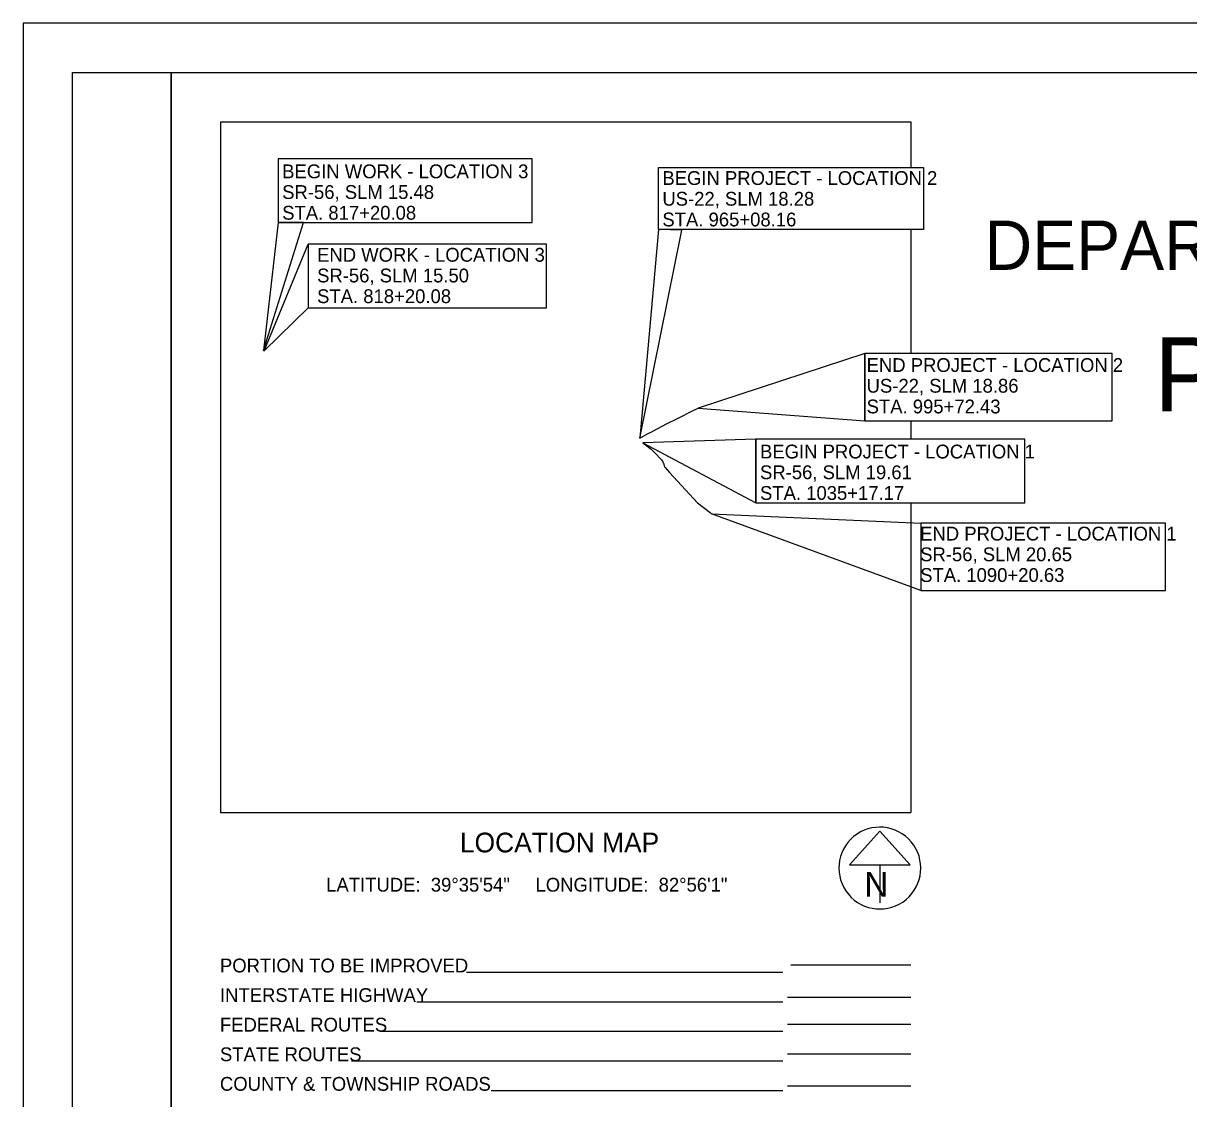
# Model space of a CAD drawing. Extents: x 0 to 34, y 0 to 22.
# Drawn here: x 0 to 11.82, y 11.1 to 22 of the extents above; entities that cross this region are included whole.
import ezdxf

# ---------------------------------------------------------------- set-up
doc = ezdxf.new("R2010")
doc.units = 0
for name, color, linetype in [('GM_X_State_Route', 7, 'Continuous'), ('GM_X_US_Route', 7, 'Continuous'), ('SH_Border', 7, 'Continuous'), ('SH_Cut_Line', 7, 'Continuous'), ('SH_Data', 7, 'Continuous'), ('SH_Text', 7, 'Continuous')]:
    doc.layers.add(name, color=color, linetype=linetype)

msp = doc.modelspace()

# ---------------------------------------------------------------- linework, layer by layer
at = {"layer": 'GM_X_State_Route'}
msp.add_line((2.437, 18.683), (2.441, 18.68), dxfattribs=at)
for points in [[(6.282, 17.747), (6.309, 17.727), (6.365, 17.682), (6.372, 17.676), (6.41, 17.637), (6.464, 17.582), (6.471, 17.575), (6.483, 17.553)], [(6.483, 17.553), (6.488, 17.545), (6.491, 17.54), (6.499, 17.518), (6.503, 17.503), (6.508, 17.497), (6.553, 17.447), (6.593, 17.403)], [(6.593, 17.403), (6.835, 17.138), (6.963, 17.039), (6.977, 17.025)]]:
    msp.add_lwpolyline(points, dxfattribs=at)
at = {"layer": 'GM_X_US_Route'}
for p, q in [((6.778, 18.067), (6.844, 18.099)), ((6.731, 18.044), (6.778, 18.067)), ((6.375, 17.86), (6.483, 17.92)), ((6.483, 17.92), (6.516, 17.937))]:
    msp.add_line(p, q, dxfattribs=at)
for points in [[(6.516, 17.937), (6.561, 17.959), (6.593, 17.974)], [(6.593, 17.974), (6.694, 18.025), (6.731, 18.044)], [(6.253, 17.794), (6.324, 17.834), (6.35, 17.847), (6.373, 17.859), (6.375, 17.86)]]:
    msp.add_lwpolyline(points, dxfattribs=at)
at = {"layer": 'SH_Border'}
for points in [[(0.5, 21.5), (1.5, 21.5), (1.5, 0.5), (0.5, 0.5)], [(1.5, 21.5), (33.5, 21.5), (33.5, 0.5), (1.5, 0.5)]]:
    msp.add_lwpolyline(points, close=True, dxfattribs=at)
at = {"layer": 'SH_Cut_Line'}
msp.add_lwpolyline([(0, 0), (34, 0), (34, 22), (0, 22)], close=True, dxfattribs=at)
at = {"layer": 'SH_Data'}
for p, q in [((2, 21), (9, 21)), ((2, 21), (2, 14)), ((9, 21), (9, 20.539)), ((9, 19.908), (9, 18.652)), ((9, 17.968), (9, 17.786)), ((9, 17.138), (9, 14)), ((2, 14), (9, 14)), ((8.685, 13.809), (8.377, 13.468)), ((8.992, 13.468), (8.685, 13.809)), ((8.377, 13.468), (8.992, 13.468)), ((8.685, 13.468), (8.685, 13.081)), ((8.685, 13.435), (8.685, 13.435)), ((8.685, 13.435), (8.685, 13.435)), ((7.783, 12.455), (9, 12.455)), ((7.7, 12.377), (4.494, 12.377)), ((7.7, 12.077), (3.99, 12.077)), ((9, 12.121), (7.75, 12.121)), ((9, 11.849), (7.75, 11.849)), ((7.7, 11.777), (3.619, 11.777)), ((7.7, 11.477), (3.329, 11.477)), ((9, 11.549), (7.75, 11.549)), ((7.7, 11.177), (4.745, 11.177)), ((9, 11.222), (7.75, 11.222))]:
    msp.add_line(p, q, dxfattribs=at)
msp.add_arc((8.685, 13.435), 0.415, 129.7798, 129.7633, dxfattribs=at)
at = {"layer": 'SH_Text'}
for points in [[(5.16, 20.627), (2.584, 20.627), (2.584, 19.98), (5.16, 19.98)], [(6.44, 20.539), (9.127, 20.539), (9.127, 19.908), (6.44, 19.908)], [(2.584, 19.98), (2.437, 18.683), (2.84, 19.98)], [(6.44, 19.908), (6.253, 17.794), (6.678, 19.903)], [(2.89, 19.114), (2.441, 18.68), (2.89, 19.761)], [(5.306, 19.761), (2.89, 19.761), (2.89, 19.114), (5.306, 19.114)], [(8.532, 18.651), (6.844, 18.099), (8.532, 17.969)], [(11.041, 18.651), (8.532, 18.651), (8.532, 17.969), (11.041, 17.969)], [(7.428, 17.785), (6.282, 17.747), (7.428, 17.138)], [(10.156, 17.785), (7.428, 17.785), (7.428, 17.138), (10.156, 17.138)], [(9.101, 16.25), (6.977, 17.025), (9.101, 16.931)], [(11.582, 16.931), (9.101, 16.931), (9.101, 16.25), (11.582, 16.25)]]:
    msp.add_lwpolyline(points, close=True, dxfattribs=at)

# ---------------------------------------------------------------- texts
at = {"layer": 'SH_Data'}
msp.add_text('N', height=0.25, dxfattribs=at).set_placement((8.529, 13.144))
at = {"layer": 'SH_Text'}
for s, height, p in [('BEGIN WORK - LOCATION 3', 0.14, (2.625, 20.429)), ('BEGIN PROJECT - LOCATION 2', 0.14, (6.48, 20.361)), ('SR-56, SLM 15.48', 0.14, (2.625, 20.219)), ('US-22, SLM 18.28', 0.14, (6.48, 20.151)), ('STA. 817+20.08', 0.14, (2.625, 20.009)), ('STA. 965+08.16', 0.14, (6.48, 19.941)), ('DEPARTMENT OF TRANSPORTATION', 0.5, (9.747, 19.5)), ('END WORK - LOCATION 3', 0.14, (2.979, 19.583)), ('SR-56, SLM 15.50', 0.14, (2.979, 19.373)), ('STA. 818+20.08', 0.14, (2.979, 19.163)), ('PIC-56-(15.48) (19.61),', 0.75, (11.467, 18.067)), ('END PROJECT - LOCATION 2', 0.14, (8.551, 18.465)), ('US-22, SLM 18.86', 0.14, (8.551, 18.255)), ('STA. 995+72.43', 0.14, (8.551, 18.045)), ('BEGIN PROJECT - LOCATION 1', 0.14, (7.47, 17.588)), ('SR-56, SLM 19.61', 0.14, (7.47, 17.378)), ('STA. 1035+17.17', 0.14, (7.47, 17.168)), ('END PROJECT - LOCATION 1', 0.14, (9.094, 16.756)), ('SR-56, SLM 20.65', 0.14, (9.094, 16.546)), ('STA. 1090+20.63', 0.14, (9.094, 16.336)), ('LOCATION MAP', 0.2, (4.427, 13.594)), ('LATITUDE:  39°35\'54"     LONGITUDE:  82°56\'1"', 0.14, (3.071, 13.196)), ('PORTION TO BE IMPROVED', 0.14, (1.994, 12.377)), ('INTERSTATE HIGHWAY', 0.14, (1.994, 12.077)), ('FEDERAL ROUTES', 0.14, (1.994, 11.777)), ('STATE ROUTES', 0.14, (1.994, 11.477)), ('COUNTY & TOWNSHIP ROADS', 0.14, (1.994, 11.177))]:
    msp.add_text(s, height=height, dxfattribs=at).set_placement(p)

doc.saveas('drawing.dxf')
